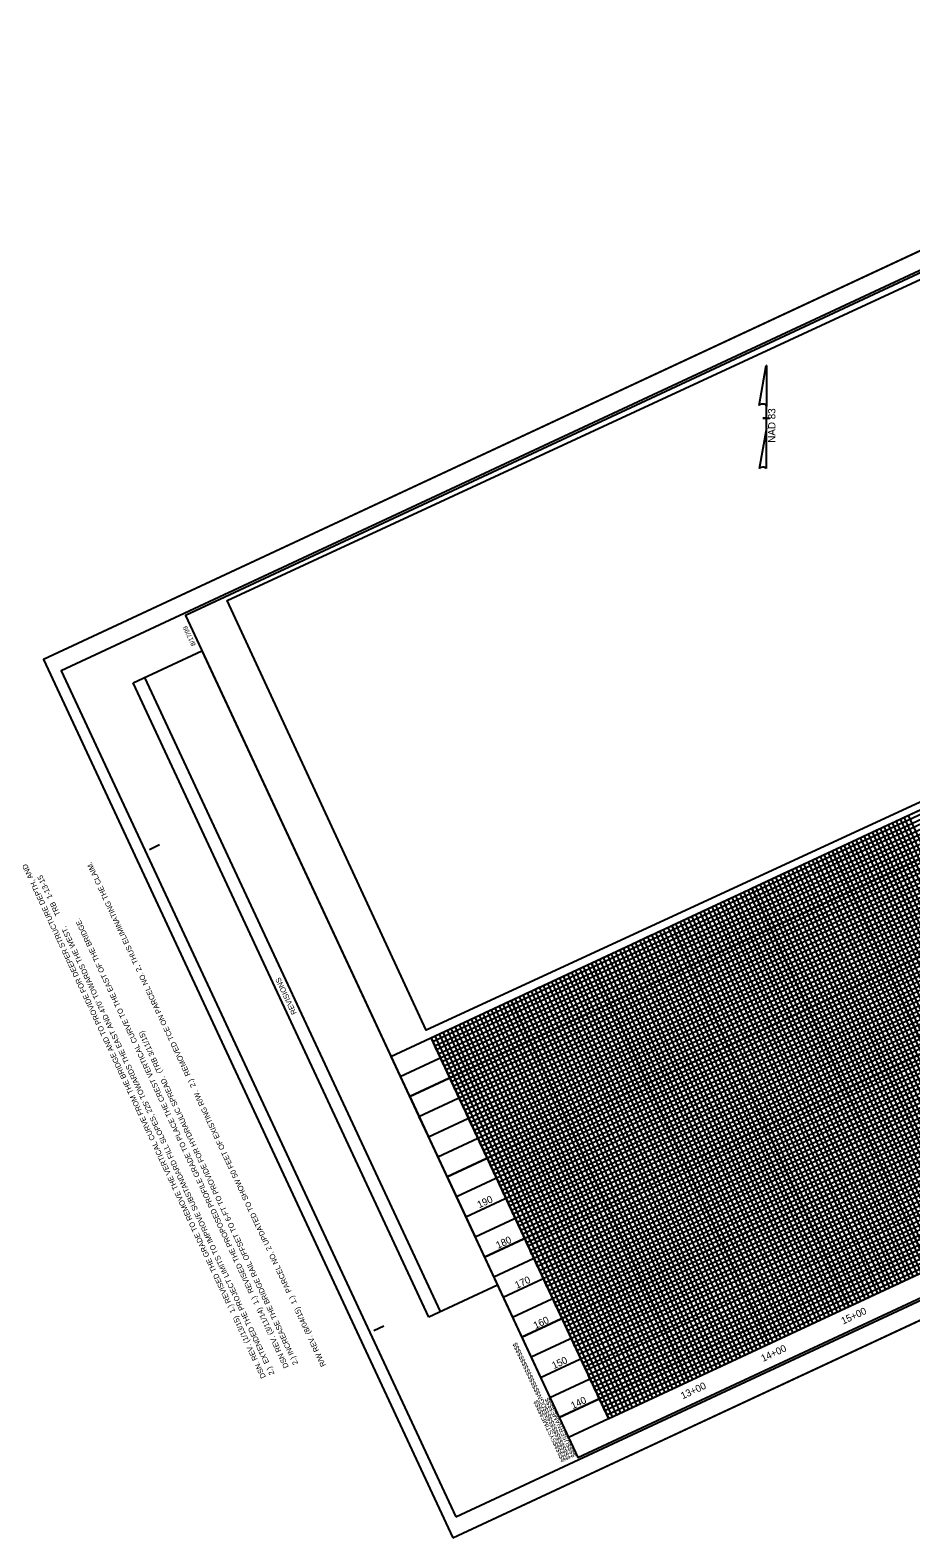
# Model space of a CAD drawing. Extents: x 2320593 to 2322597, y 921119 to 922832.
# Drawn here: x 2320593 to 2321588, y 921119 to 922823 of the extents above; entities that cross this region are included whole.
import ezdxf

# ---------------------------------------------------------------- set-up
doc = ezdxf.new("R2010")
doc.units = 0
for name, color, linetype in [('Default', 7, 'Continuous'), ('Prop North Arrow NAD83 for Plan Sheets CELL', 7, 'Continuous'), ('Sheet Block Revision CELL', 7, 'Continuous'), ('Sheet Block System Information CELL', 7, 'Continuous'), ('Sheet Cutting Line CELL', 7, 'Continuous'), ('Sheet DOT Grid CELL', 7, 'Continuous'), ('Sheet Layout Plan Border', 7, 'Continuous'), ('Sheet Layout Profile Border Port 2', 7, 'Continuous'), ('Sheet Plan And Profile CELL', 7, 'Continuous'), ('Sheet Plot Border Inside CELL', 7, 'Continuous'), ('Sheet Plot Border Outside CELL', 7, 'Continuous'), ('Sheet Profile Grid Major CELL', 7, 'Continuous'), ('Sheet Profile Grid Middle CELL', 7, 'Continuous'), ('Sheet Profile Grid Minor CELL', 7, 'Continuous')]:
    doc.layers.add(name, color=color, linetype=linetype)

# ---------------------------------------------------------------- blocks, each defined once
blk = doc.blocks.new('SYSTEM BLOCK')
at = {"layer": 'Sheet Block System Information CELL'}
blk.add_line((0, 0), (0, 0), dxfattribs=at)
for s, p in [('$$$$$$$$$$$$$$$$DGN$$$$$$$$$$$$$$$$', (-0.153, 0.04725)), ('$$$$$$SYSTIME$$$$$', (-0.274, 0.04725)), ('$$$$USERNAME$$$$', (-0.0215, 0.0475))]:
    blk.add_text(s, height=0.105, rotation=90, dxfattribs=at).set_placement(p)

msp = doc.modelspace()

# ---------------------------------------------------------------- linework, layer by layer
at = {"layer": 'Prop North Arrow NAD83 for Plan Sheets CELL'}
for p, q in [((2321417.1, 922398.7), (2321425.1, 922443.9)), ((2321425.2, 922443.9), (2321425.1, 922443.9)), ((2321425.2, 922443.9), (2321425.1, 922443.9)), ((2321425.2, 922443.9), (2321425.2, 922397.3)), ((2321425.2, 922373.1), (2321425.2, 922398.6)), ((2321425.2, 922397.3), (2321425.2, 922398.6)), ((2321421.3, 922384.4), (2321421.2, 922384.4)), ((2321421.3, 922384.4), (2321429.1, 922384.4)), ((2321424.7, 922384.4), (2321421.3, 922384.4)), ((2321425.2, 922373.1), (2321417, 922327)), ((2321425.2, 922327.2), (2321425.2, 922373.1))]:
    msp.add_line(p, q, dxfattribs=at)
for centre, start_param, end_param in [((2321421.1, 922398.2), 0.216388, 2.908219), ((2321421.1, 922326.9), 0.201328, 3.141593)]:
    msp.add_ellipse(centre, major_axis=(4.12, -0.03), ratio=0.461098, start_param=start_param, end_param=end_param, dxfattribs=at)
at = {"layer": 'Sheet Block Revision CELL'}
for p, q in [((2320709.8, 922085.1), (2320787.3, 922121.2)), ((2320787.3, 922121.2), (2321121.4, 921404.6)), ((2321057, 921374.6), (2320723, 922091.2)), ((2321043.8, 921368.4), (2320709.8, 922085.1)), ((2321121.4, 921404.6), (2321043.8, 921368.4))]:
    msp.add_line(p, q, dxfattribs=at)
at = {"layer": 'Sheet Cutting Line CELL'}
for p, q in [((2322134.1, 922822.7), (2320608.2, 922111.4)), ((2320608.2, 922111.4), (2321070.8, 921119)), ((2321070.8, 921119), (2322596.7, 921830.2))]:
    msp.add_line(p, q, dxfattribs=at)
at = {"layer": 'Sheet DOT Grid CELL'}
for p, q in [((2321001, 921662.9), (2322360.5, 922296.6)), ((2321022.1, 921617.6), (2322381.6, 922251.3)), ((2321043.2, 921572.3), (2322402.8, 922206)), ((2321064.3, 921526.9), (2322423.9, 922160.7)), ((2321085.5, 921481.6), (2322445, 922115.3)), ((2321106.6, 921436.3), (2322466.1, 922070)), ((2321127.7, 921391), (2322487.3, 922024.7)), ((2321148.8, 921345.7), (2322508.4, 921979.4)), ((2321170, 921300.3), (2322529.5, 921934.1)), ((2321544.8, 921916.4), (2321745.5, 921485.9)), ((2321191.1, 921255), (2322550.6, 921888.7)), ((2321499.5, 921895.3), (2321700.1, 921464.7)), ((2321454.1, 921874.1), (2321654.8, 921443.6)), ((2321408.8, 921853), (2321609.5, 921422.5)), ((2321363.5, 921831.9), (2321564.2, 921401.4)), ((2321318.2, 921810.8), (2321518.9, 921380.2)), ((2321272.9, 921789.6), (2321473.5, 921359.1)), ((2321227.6, 921768.5), (2321428.2, 921338)), ((2321182.2, 921747.4), (2321382.9, 921316.9)), ((2321136.9, 921726.3), (2321337.6, 921295.7)), ((2321091.6, 921705.1), (2321292.3, 921274.6)), ((2321046.3, 921684), (2321247, 921253.5))]:
    msp.add_line(p, q, dxfattribs=at)
at = {"layer": 'Sheet Layout Plan Border'}
msp.add_lwpolyline([(2322313.3, 922280), (2321040.8, 921692.7), (2320815.9, 922178.3), (2322085.9, 922766.6)], close=True, dxfattribs=at)
at = {"layer": 'Sheet Layout Profile Border Port 2'}
msp.add_lwpolyline([(2321046.3, 921684), (2322315.2, 922275.5), (2322515.9, 921845), (2321247, 921253.5)], close=True, dxfattribs=at)
at = {"layer": 'Sheet Plan And Profile CELL'}
for p, q in [((2320728, 921897), (2320739.3, 921902.3)), ((2322561.2, 921866.1), (2321201.6, 921232.4)), ((2320981.5, 921353.2), (2320992.8, 921358.4)), ((2321212.2, 921209.7), (2321212.2, 921209.7)), ((2321212.2, 921209.7), (2321212.2, 921209.7)), ((2321212.2, 921209.7), (2321212.2, 921209.7)), ((2321212.2, 921209.7), (2321212.2, 921209.7)), ((2321212.2, 921209.7), (2321212.2, 921209.7))]:
    msp.add_line(p, q, dxfattribs=at)
msp.add_lwpolyline([(2322128.2, 922795.1), (2320768.6, 922161.4), (2321212.2, 921209.7), (2322571.8, 921843.4)], close=True, dxfattribs=at)
at = {"layer": 'Sheet Plot Border Inside CELL'}
msp.add_lwpolyline([(2321074.1, 921142.6), (2322584.1, 921846.4), (2322138.4, 922802.7), (2320628.4, 922098.8)], close=True, dxfattribs=at)
at = {"layer": 'Sheet Plot Border Outside CELL'}
msp.add_lwpolyline([(2321070.8, 921119), (2322596.7, 921830.2), (2322134.1, 922822.7), (2320608.2, 922111.4)], close=True, dxfattribs=at)
at = {"layer": 'Sheet Profile Grid Major CELL'}
for points in [[(2321001, 921662.9), (2322360.5, 922296.6)], [(2322381.6, 922251.3), (2321022.1, 921617.6), (2321043.2, 921572.3), (2322402.8, 922206)], [(2322423.9, 922160.7), (2321064.3, 921526.9), (2321085.5, 921481.6), (2322445, 922115.3)], [(2322466.1, 922070), (2321106.6, 921436.3), (2321127.7, 921391), (2322487.3, 922024.7)], [(2322508.4, 921979.4), (2321148.8, 921345.7), (2321170, 921300.3), (2322529.5, 921934.1)], [(2321700.1, 921464.7), (2321499.5, 921895.3), (2321544.8, 921916.4), (2321745.5, 921485.9)], [(2322550.6, 921888.7), (2321191.1, 921255)], [(2321609.5, 921422.5), (2321408.8, 921853), (2321454.1, 921874.1), (2321654.8, 921443.6)], [(2321518.9, 921380.2), (2321318.2, 921810.8), (2321363.5, 921831.9), (2321564.2, 921401.4)], [(2321428.2, 921338), (2321227.6, 921768.5), (2321272.9, 921789.6), (2321473.5, 921359.1)], [(2321337.6, 921295.7), (2321136.9, 921726.3), (2321182.2, 921747.4), (2321382.9, 921316.9)], [(2321247, 921253.5), (2321046.3, 921684), (2321091.6, 921705.1), (2321292.3, 921274.6)], [(2321001, 921662.9), (2321201.6, 921232.4)]]:
    msp.add_lwpolyline(points, dxfattribs=at)
at = {"layer": 'Sheet Profile Grid Middle CELL'}
for p, q in [((2321011.5, 921640.2), (2322371.1, 922274)), ((2322392.2, 922228.6), (2321032.6, 921594.9)), ((2321053.8, 921549.6), (2322413.3, 922183.3)), ((2322434.5, 922138), (2321074.9, 921504.3)), ((2321096, 921459), (2322455.6, 922092.7)), ((2322476.7, 922047.4), (2321117.1, 921413.6)), ((2321138.3, 921368.3), (2322497.8, 922002)), ((2322518.9, 921956.7), (2321159.4, 921323)), ((2321180.5, 921277.7), (2322540.1, 921911.4)), ((2321032.6, 921594.9), (2321053.8, 921549.6)), ((2321074.9, 921504.3), (2321096, 921459)), ((2321117.1, 921413.6), (2321138.3, 921368.3)), ((2321159.4, 921323), (2321180.5, 921277.7))]:
    msp.add_line(p, q, dxfattribs=at)
for points in [[(2321722.8, 921475.3), (2321522.1, 921905.8), (2321567.4, 921926.9), (2321768.1, 921496.4)], [(2321632.2, 921433), (2321431.5, 921863.6), (2321476.8, 921884.7), (2321677.5, 921454.2)], [(2321541.5, 921390.8), (2321340.8, 921821.3), (2321386.2, 921842.4), (2321586.8, 921411.9)], [(2321450.9, 921348.5), (2321250.2, 921779.1), (2321295.5, 921800.2), (2321496.2, 921369.7)], [(2321360.3, 921306.3), (2321159.6, 921736.8), (2321204.9, 921757.9), (2321405.6, 921327.4)], [(2321269.6, 921264.1), (2321068.9, 921694.6), (2321114.3, 921715.7), (2321314.9, 921285.2)]]:
    msp.add_lwpolyline(points, dxfattribs=at)
at = {"layer": 'Sheet Profile Grid Minor CELL'}
for points in [[(2322317.3, 922271), (2321048.4, 921679.5)], [(2322321.5, 922261.9), (2321052.6, 921670.4), (2321050.5, 921675), (2322319.4, 922266.4)], [(2322327.9, 922248.3), (2321059, 921656.8), (2321056.8, 921661.4), (2321054.7, 921665.9), (2322323.6, 922257.4)], [(2322332.1, 922239.2), (2321063.2, 921647.8), (2321061.1, 921652.3), (2322330, 922243.8)], [(2322338.4, 922225.6), (2321069.5, 921634.2), (2321067.4, 921638.7), (2321065.3, 921643.2), (2322334.2, 922234.7)], [(2322342.7, 922216.6), (2321073.7, 921625.1), (2321071.6, 921629.6), (2322340.5, 922221.1)], [(2322349, 922203), (2321080.1, 921611.5), (2321078, 921616), (2321075.9, 921620.6), (2322344.8, 922212)], [(2322353.2, 922193.9), (2321084.3, 921602.4), (2321082.2, 921607), (2322351.1, 922198.4)], [(2321090.6, 921588.8), (2321088.5, 921593.4), (2321086.4, 921597.9), (2322355.3, 922189.4)], [(2322361.7, 922175.8), (2321092.8, 921584.3), (2321090.6, 921588.8), (2322359.6, 922180.3)], [(2322365.9, 922166.7), (2321097, 921575.3), (2321094.9, 921579.8), (2322363.8, 922171.3)], [(2322372.2, 922153.1), (2321103.3, 921561.7), (2321101.2, 921566.2), (2322370.1, 922157.7)], [(2322376.5, 922144.1), (2321107.5, 921552.6), (2321105.4, 921557.1), (2322374.3, 922148.6)], [(2322382.8, 922130.5), (2321113.9, 921539), (2321111.8, 921543.5), (2322380.7, 922135)], [(2322387, 922121.4), (2321118.1, 921529.9), (2321116, 921534.5), (2322384.9, 922125.9)], [(2322393.4, 922107.8), (2321124.4, 921516.3), (2321122.3, 921520.9), (2322391.2, 922112.3)], [(2322397.6, 922098.7), (2321128.7, 921507.3), (2321126.5, 921511.8), (2322395.5, 922103.3)], [(2322403.9, 922085.2), (2321135, 921493.7), (2321132.9, 921498.2), (2322401.8, 922089.7)], [(2322408.1, 922076.1), (2321139.2, 921484.6), (2321137.1, 921489.1), (2322406, 922080.6)], [(2322414.5, 922062.5), (2321145.6, 921471), (2321143.4, 921475.6), (2322412.4, 922067)], [(2322418.7, 922053.4), (2321149.8, 921462), (2321147.7, 921466.5), (2322416.6, 922058)], [(2322425, 922039.8), (2321156.1, 921448.4), (2321154, 921452.9), (2322422.9, 922044.4)], [(2322429.3, 922030.8), (2321160.3, 921439.3), (2321158.2, 921443.8), (2322427.2, 922035.3)], [(2322435.6, 922017.2), (2321166.7, 921425.7), (2321164.6, 921430.2), (2322433.5, 922021.7)], [(2322439.8, 922008.1), (2321170.9, 921416.6), (2321168.8, 921421.2), (2322437.7, 922012.6)], [(2322446.2, 921994.5), (2321177.2, 921403), (2321175.1, 921407.6), (2322444.1, 921999)], [(2322450.4, 921985.4), (2321181.5, 921394), (2321179.4, 921398.5), (2322448.3, 921990)], [(2322456.7, 921971.9), (2321187.8, 921380.4), (2321185.7, 921384.9), (2322454.6, 921976.4)], [(2322461, 921962.8), (2321192, 921371.3), (2321189.9, 921375.8), (2322458.8, 921967.3)], [(2322467.3, 921949.2), (2321198.4, 921357.7), (2321196.3, 921362.3), (2322465.2, 921953.7)], [(2322471.5, 921940.1), (2321202.6, 921348.7), (2321200.5, 921353.2), (2322469.4, 921944.7)], [(2322477.9, 921926.5), (2321208.9, 921335.1), (2321206.8, 921339.6), (2322475.7, 921931.1)], [(2322482.1, 921917.5), (2321213.2, 921326), (2321211, 921330.5), (2322480, 921922)], [(2321750, 921488), (2321549.3, 921918.5), (2321553.8, 921920.6), (2321754.5, 921490.1)], [(2321759.1, 921492.2), (2321558.4, 921922.7), (2321562.9, 921924.8), (2321763.6, 921494.3)], [(2321772.7, 921498.5), (2321572, 921929.1), (2321576.5, 921931.2), (2321777.2, 921500.6)], [(2321781.7, 921502.8), (2321581, 921933.3), (2321585.6, 921935.4), (2321786.2, 921504.9)], [(2321219.5, 921312.4), (2321217.4, 921316.9), (2322486.3, 921908.4)], [(2321244.8, 921258), (2322513.8, 921849.5), (2322511.7, 921854), (2321242.7, 921262.6), (2321240.6, 921267.1), (2322509.5, 921858.6), (2322507.4, 921863.1), (2321238.5, 921271.6), (2321236.4, 921276.1), (2321234.3, 921280.7), (2322503.2, 921872.2), (2322501.1, 921876.7), (2321232.2, 921285.2), (2321230.1, 921289.7), (2322499, 921881.2), (2322496.9, 921885.7), (2321227.9, 921294.3), (2321225.8, 921298.8), (2321223.7, 921303.3), (2322492.6, 921894.8), (2322490.5, 921899.3), (2321221.6, 921307.9), (2321219.5, 921312.4), (2322488.4, 921903.9)], [(2321713.7, 921471.1), (2321513.1, 921901.6), (2321517.6, 921903.7), (2321718.3, 921473.2)], [(2321727.3, 921477.4), (2321526.7, 921907.9), (2321531.2, 921910), (2321731.9, 921479.5)], [(2321736.4, 921481.6), (2321535.7, 921912.2), (2321540.3, 921914.3), (2321740.9, 921483.7)], [(2321682, 921456.3), (2321481.3, 921886.8), (2321485.9, 921888.9), (2321686.5, 921458.4)], [(2321691.1, 921460.5), (2321490.4, 921891), (2321494.9, 921893.1), (2321695.6, 921462.6)], [(2321704.7, 921466.8), (2321504, 921897.4), (2321508.5, 921899.5), (2321709.2, 921469)], [(2321636.7, 921435.2), (2321436, 921865.7), (2321440.5, 921867.8), (2321641.2, 921437.3)], [(2321645.8, 921439.4), (2321445.1, 921869.9), (2321449.6, 921872), (2321650.3, 921441.5)], [(2321659.4, 921445.7), (2321458.7, 921876.2), (2321463.2, 921878.4), (2321663.9, 921447.8)], [(2321668.4, 921449.9), (2321467.7, 921880.5), (2321472.3, 921882.6), (2321673, 921452.1)], [(2321600.4, 921418.3), (2321399.8, 921848.8), (2321404.3, 921850.9), (2321605, 921420.4)], [(2321614, 921424.6), (2321413.4, 921855.1), (2321417.9, 921857.2), (2321618.6, 921426.7)], [(2321623.1, 921428.8), (2321422.4, 921859.3), (2321427, 921861.5), (2321627.6, 921430.9)], [(2321568.7, 921403.5), (2321368, 921834), (2321372.6, 921836.1), (2321573.3, 921405.6)], [(2321577.8, 921407.7), (2321377.1, 921838.2), (2321381.6, 921840.3), (2321582.3, 921409.8)], [(2321591.4, 921414), (2321390.7, 921844.6), (2321395.2, 921846.7), (2321595.9, 921416.1)], [(2321532.5, 921386.6), (2321331.8, 921817.1), (2321336.3, 921819.2), (2321537, 921388.7)], [(2321546.1, 921392.9), (2321345.4, 921823.4), (2321349.9, 921825.5), (2321550.6, 921395)], [(2321555.1, 921397.1), (2321354.4, 921827.7), (2321359, 921829.8), (2321559.7, 921399.2)], [(2321500.7, 921371.8), (2321300.1, 921802.3), (2321304.6, 921804.4), (2321505.3, 921373.9)], [(2321509.8, 921376), (2321309.1, 921806.5), (2321313.7, 921808.6), (2321514.3, 921378.1)], [(2321523.4, 921382.3), (2321322.7, 921812.9), (2321327.3, 921815), (2321527.9, 921384.5)], [(2321455.4, 921350.7), (2321254.7, 921781.2), (2321259.3, 921783.3), (2321460, 921352.8)], [(2321464.5, 921354.9), (2321263.8, 921785.4), (2321268.3, 921787.5), (2321469, 921357)], [(2321478.1, 921361.2), (2321277.4, 921791.7), (2321281.9, 921793.9), (2321482.6, 921363.3)], [(2321487.1, 921365.4), (2321286.5, 921796), (2321291, 921798.1), (2321491.7, 921367.6)], [(2321419.2, 921333.8), (2321218.5, 921764.3), (2321223, 921766.4), (2321423.7, 921335.9)], [(2321432.8, 921340.1), (2321232.1, 921770.6), (2321236.6, 921772.7), (2321437.3, 921342.2)], [(2321441.8, 921344.3), (2321241.1, 921774.8), (2321245.7, 921777), (2321446.4, 921346.4)], [(2321387.4, 921319), (2321186.8, 921749.5), (2321191.3, 921751.6), (2321392, 921321.1)], [(2321396.5, 921323.2), (2321195.8, 921753.7), (2321200.4, 921755.8), (2321401, 921325.3)], [(2321410.1, 921329.5), (2321209.4, 921760.1), (2321214, 921762.2), (2321414.6, 921331.6)], [(2321351.2, 921302.1), (2321150.5, 921732.6), (2321155, 921734.7), (2321355.7, 921304.2)], [(2321364.8, 921308.4), (2321164.1, 921738.9), (2321168.6, 921741.1), (2321369.3, 921310.5)], [(2321373.8, 921312.6), (2321173.2, 921743.2), (2321177.7, 921745.3), (2321378.4, 921314.7)], [(2321319.5, 921287.3), (2321118.8, 921717.8), (2321123.3, 921719.9), (2321324, 921289.4)], [(2321328.5, 921291.5), (2321127.9, 921722), (2321132.4, 921724.2), (2321333.1, 921293.6)], [(2321342.1, 921297.8), (2321141.4, 921728.4), (2321146, 921730.5), (2321346.7, 921300)], [(2321274.1, 921266.2), (2321073.5, 921696.7), (2321078, 921698.8), (2321278.7, 921268.3)], [(2321283.2, 921270.4), (2321082.5, 921700.9), (2321087.1, 921703), (2321287.7, 921272.5)], [(2321296.8, 921276.7), (2321096.1, 921707.3), (2321100.7, 921709.4), (2321301.3, 921278.8)], [(2321305.9, 921281), (2321105.2, 921711.5), (2321109.7, 921713.6), (2321310.4, 921283.1)], [(2321251.5, 921255.6), (2321050.8, 921686.1), (2321055.3, 921688.2), (2321256, 921257.7)], [(2321260.6, 921259.8), (2321059.9, 921690.4), (2321064.4, 921692.5), (2321265.1, 921261.9)]]:
    msp.add_lwpolyline(points, dxfattribs=at)

# ---------------------------------------------------------------- block references
at = {"layer": 'Sheet Block System Information CELL', "xscale": 49.99999999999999, "yscale": 50, "rotation": 24.991298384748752}
msp.add_blockref('SYSTEM BLOCK', (2321212.2, 921209.7), dxfattribs=at)

# ---------------------------------------------------------------- texts
at = {"layer": 'Default'}
for s, p in [('190', (2321100.7, 921491.3)), ('180', (2321121.9, 921445.5)), ('170', (2321143.3, 921400.3)), ('15+00', (2321512, 921359.9)), ('160', (2321164.2, 921354.9)), ('150', (2321185.1, 921309.5)), ('14+00', (2321421.5, 921317.7)), ('13+00', (2321330.7, 921275.4)), ('140', (2321206.5, 921264.3))]:
    msp.add_text(s, height=8, rotation=24.9913, dxfattribs=at).set_placement(p)
at = {"layer": 'Prop North Arrow NAD83 for Plan Sheets CELL'}
msp.add_text('NAD 83', height=8.29, rotation=89.9913, dxfattribs=at).set_placement((2321435.4, 922356.5))
at = {"layer": 'Sheet Block Revision CELL'}
for s, p in [('DSN. REV. (1/13/15)  1.) REVISED THE GRADE TO REMOVE THE VERTICAL CURVE FROM THE BRIDGE AND TO PROVIDE FOR DEEPER STRUCTURE DEPTH, AND             ', (2320859.8, 921300.8)), ('R/W REV. (8/04/15)  1.)  PARCEL NO. 2 UPDATED TO SHOW 50 FEET OF EXISTING R/W.  2.)  REMOVED TCE ON PARCEL NO. 2, THUS ELIMINATING THE CLAIM.               ', (2320927.6, 921314)), ("2.)  EXTENDED THE PROJECT LIMITS TO IMPROVE SUBSTANDARD FILL SLOPES, 225' TOWARDS THE EAST AND 470' TOWARDS THE WEST.      TRB  1-13-15            ", (2320869.5, 921304.4)), ('DSN REV. (3/11/14)  1.)  REVISED THE PROPOSED PROFILE GRADE TO PLACE THE CREST VERTICAL CURVE TO THE EAST OF THE BRIDGE.        ', (2320885.6, 921312.3)), ('REVISIONS', (2320894.6, 921711.9)), ('2.) INCREASE THE BRIDGE RAIL OFFSET TO 6-FT TO PROVIDE FOR HYDRAULIC SPREAD.  (TRB 3/11/15)                                     ', (2320896.3, 921316))]:
    msp.add_text(s, height=6, rotation=114.9913, dxfattribs=at).set_placement(p)
at = {"layer": 'Sheet Plan And Profile CELL'}
msp.add_text('8/17/99', height=5.25, rotation=114.9913, dxfattribs=at).set_placement((2320780.5, 922128.1))

doc.saveas('drawing.dxf')
